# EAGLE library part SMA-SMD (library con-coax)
SMA 50 Ohm Straight Jack Receptacle - Surface Mount www.johnsoncomponents.com Source: http://catalog.digikey.com .. 142-0711-201, 205, 202, 206.pdf
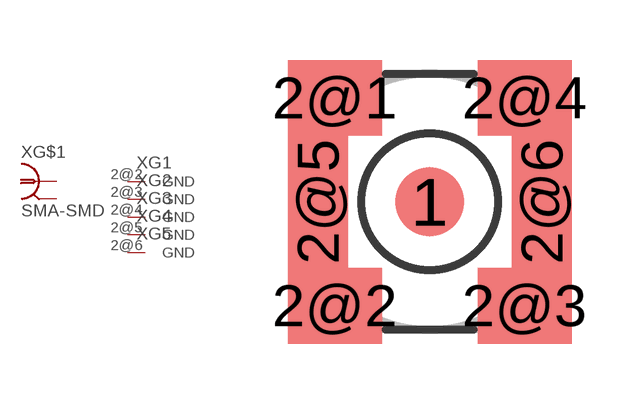
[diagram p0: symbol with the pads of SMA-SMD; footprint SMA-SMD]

Designator prefix X; gates G$1=BU-BNC G1=PIN_GND G2=PIN_GND G3=PIN_GND G4=PIN_GND G5=PIN_GND

## SMA-SMD (OC_FARNELL: unknown; OC_NEWARK: unknown)  [SMA-SMD]
1  G$1:1  pas
2@1  G$1:GND  pwr
2@2  G1:GND  pwr
2@3  G2:GND  pwr
2@4  G3:GND  pwr
2@5  G4:GND  pwr
2@6  G5:GND  pwr

## Footprint SMA-SMD (pad centres in mm)
SMA 50 Ohm Straight Jack Receptacle - Surface Mount www.johnsoncomponents.com Source: http://catalog.digikey.com .. 142-0711-201, 205, 202, 206.pdf
smd 1.73 x 1.73: 1 0,0
smd 2.35 x 1.9: 2@1 -2.375,2.6; 2@2 -2.375,-2.6; 2@3 2.375,-2.6; 2@4 2.375,2.6
smd 1.5 x 3.4: 2@5 -2.8,0; 2@6 2.8,0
